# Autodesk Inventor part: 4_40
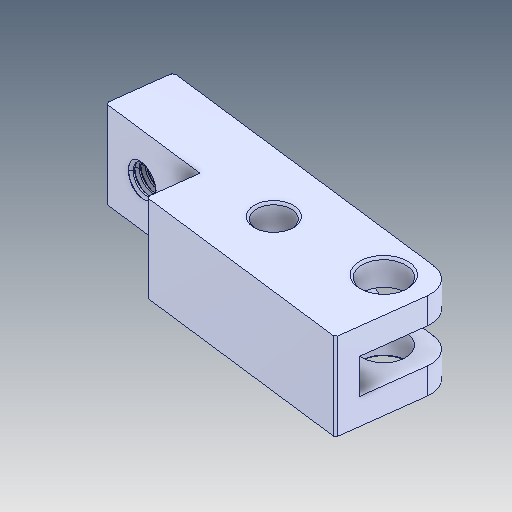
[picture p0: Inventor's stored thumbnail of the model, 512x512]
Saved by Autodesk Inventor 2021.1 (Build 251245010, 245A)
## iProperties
Created: 2021-06
Part Number: 4_40
Material: Ogólny
Document SubType Name: Modeling
Designer: user
Density: 1 g/cm^3
Appearance: Domyślna
Author: user
Revision Number: ÈÎºÎ
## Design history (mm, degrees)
feature "ÊäÈë1"
node "Bryła1"
